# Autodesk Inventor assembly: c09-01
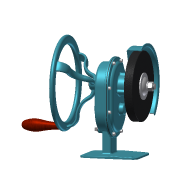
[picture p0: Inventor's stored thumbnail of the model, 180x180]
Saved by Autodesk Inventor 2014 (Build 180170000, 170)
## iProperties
Created: 2010-12
Part Number: c09-01
Document SubType Name: Assembly
Designer: Thom Tremblay
Author: Thom Tremblay
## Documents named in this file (27)
- C:\Inventor 2014 Essentials\Assemblies\Chapter 09\c09-01.iam
- C:\Inventor 2014 Essentials\Content Center Files\en-US\ANSI B93.98M\ANSI_B93.98M - 15x35x7-Type 2.ipt
- C:\Inventor 2014 Essentials\Content Center Files\en-US\SKF B - angular contact\SKF B7202 BE.ipt
- C:\Inventor 2014 Essentials\Content Center Files\en-US\IS 7483\IS 7483 - M4 x 8.ipt
- C:\Inventor 2014 Essentials\Content Center Files\en-US\ISO 2795  F\ISO 2795 - 10 x 14 x 10F.ipt
- C:\Inventor 2014 Essentials\Content Center Files\en-US\STN 022930\STN 022930 - 10.ipt
- C:\Inventor 2014 Essentials\Content Center Files\en-US\STN 022930\STN 022930 - 15.ipt
- C:\Inventor 2014 Essentials\Content Center Files\en-US\DIN 128\DIN 128 - A12.ipt
- C:\Inventor 2014 Essentials\Content Center Files\en-US\ISO 4032\ISO 4032 - M12ISO.ipt
- C:\Inventor 2014 Essentials\Content Center Files\en-US\ISO 4145 T8\ISO 4145 Plug T8 1_8.ipt
- C:\Inventor 2014 Essentials\Parts\Chapter 09\c09-01.ipt
- C:\Inventor 2014 Essentials\Parts\Chapter 09\c09-02.ipt
- C:\Inventor 2014 Essentials\Parts\Chapter 09\c09-03.ipt
- C:\Inventor 2014 Essentials\Parts\Chapter 09\c09-04.ipt
- C:\Inventor 2014 Essentials\Parts\Chapter 09\c09-05.ipt
- C:\Inventor 2014 Essentials\Parts\Chapter 09\c09-08.ipt
- C:\Inventor 2014 Essentials\Parts\Chapter 09\c09-06.ipt
- C:\Inventor 2014 Essentials\Parts\Chapter 09\c09-07.ipt
- C:\Inventor 2014 Essentials\Assemblies\Chapter 09\Design Accelerators\Shaft c09-01.iam
- C:\Inventor 2014 Essentials\Assemblies\Chapter 09\Design Accelerators\Shaft c09-02.iam
- C:\Inventor 2014 Essentials\Assemblies\Chapter 09\Design Accelerators\Shaft c09-03.iam
- C:\Inventor 2014 Essentials\Assemblies\Chapter 09\Design Accelerators\Cut Gear c09-01.iam
- C:\Inventor 2014 Essentials\Assemblies\Chapter 09\Design Accelerators\Cut Gear c09-02.iam
- C:\Inventor 2014 Essentials\Assemblies\Chapter 09\Design Accelerators\Spur Gear c09-01.iam
- C:\Inventor 2014 Essentials\Assemblies\Chapter 09\Design Accelerators\Key Connection c09-01.iam
- C:\Inventor 2014 Essentials\Assemblies\Chapter 09\Design Accelerators\Bolted Connection c09-01.iam
- C:\Inventor 2014 Essentials\Assemblies\Chapter 09\Design Accelerators\Bolted Connection c09-02.iam
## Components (31 placed, 24 different names)
1. c09-01:1 — Insert:1, Flush:3, Insert:27, Insert:28, Insert:39, Angle:19
2. c09-02:1 — Insert:1, Insert:17, Insert:18, Insert:25, Insert:26, Insert:40, Angle:19, Mate:18, Mate:19
3. ANSI/B93.98M 15x35x7-Type 2:1 — Insert:40
4. c09-03:1 — Flush:3
5. c09-04:1 — Insert:10, Angle:17, Insert:49, Mate:16, Angle:20
6. c09-05:1 — Insert:10
7. c09-08:1 — Insert:13, Insert:16, Insert:48
8. c09-08:2 — Insert:13
9. c09-06:1 — Insert:16, Angle:11
10. c09-07:1 — Insert:17, Insert:18
11. SKF B- Angular contact SKF B7202 BE:1 — Insert:25, Insert:45
12. IS 7483 M4 x 8:1
13. IS 7483 M4 x 8:2
14. ISO 2795 (Flanged) 10 x 14 x 10:1 — Insert:26
15. ISO 2795 (Flanged) 10 x 14 x 10:2 — Insert:27, Insert:46
16. ISO 2795 (Flanged) 10 x 14 x 10:3 — Insert:28, Insert:41
17. STN 022930 10:1 — Angle:16
18. STN 022930 15:1
19. STN 022930 15:2
20. DIN 128 A12:1 — Angle:10
21. ISO 4032 M12:1 — Angle:10, Angle:11, Angle:18
22. ISO 4145 Plug T8 1/8:1 — Insert:39
23. Input Shaft [sub-assembly] — Insert:41, Angle:16, Angle:17, Insert:49, Mate:17, Rotation:1, Rotation:2
24. Output Shaft:2 [sub-assembly] — Insert:45, Flush:4, Insert:48, Angle:18, Rotation:2
25. Transfer Shaft:1 [sub-assembly] — Insert:46, Mate:12, Flush:5, Angle:14, Mate:13, Angle:15, Rotation:1, Rotation:3
26. Cut Gear:1 [sub-assembly]
27. Cut Gear:2 [sub-assembly]
28. Cut Gear:3 [sub-assembly] — Mate:12, Flush:4, Angle:15, Rotation:3
29. Key Connection:1 [sub-assembly] — Flush:5, Angle:14, Mate:13
30. Housing Bolts:1 [sub-assembly] — Mate:18, Mate:19
31. Wheel Bolt [sub-assembly] — Mate:16, Mate:17, Angle:20
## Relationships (38: Insert 17, Angle 9, Mate 6, Flush 3, RelateRotation 3)
- Insert:1: c09-01:1 ↔ c09-02:1
- Flush:3: c09-01:1 ↔ c09-03:1
- Insert:10: c09-04:1 ↔ c09-05:1
- Insert:13: c09-08:1 ↔ c09-08:2
- Insert:16: c09-08:1 ↔ c09-06:1
- Insert:17: c09-02:1 ↔ c09-07:1
- Insert:18: c09-02:1 ↔ c09-07:1
- Insert:25: c09-02:1 ↔ SKF B- Angular contact SKF B7202 BE:1
- Insert:26: c09-02:1 ↔ ISO 2795 (Flanged) 10 x 14 x 10:1
- Insert:27: c09-01:1 ↔ ISO 2795 (Flanged) 10 x 14 x 10:2
- Insert:28: c09-01:1 ↔ ISO 2795 (Flanged) 10 x 14 x 10:3
- Angle:10: DIN 128 A12:1 ↔ ISO 4032 M12:1
- Angle:11: c09-06:1 ↔ ISO 4032 M12:1
- Insert:39: c09-01:1 ↔ ISO 4145 Plug T8 1/8:1
- Insert:40: c09-02:1 ↔ ANSI/B93.98M 15x35x7-Type 2:1
- Insert:41: ISO 2795 (Flanged) 10 x 14 x 10:3 ↔ Input Shaft
- Insert:45: SKF B- Angular contact SKF B7202 BE:1 ↔ Output Shaft:2
- Insert:46: ISO 2795 (Flanged) 10 x 14 x 10:2 ↔ Transfer Shaft:1
- Mate:12: Transfer Shaft:1 ↔ Cut Gear:3
- Flush:4: Output Shaft:2 ↔ Cut Gear:3
- Flush:5: Transfer Shaft:1 ↔ Key Connection:1
- Angle:14: Transfer Shaft:1 ↔ Key Connection:1
- Mate:13: Transfer Shaft:1 ↔ Key Connection:1
- Angle:15: Transfer Shaft:1 ↔ Cut Gear:3
- Angle:16: STN 022930 10:1 ↔ Input Shaft
- Angle:17: c09-04:1 ↔ Input Shaft
- Insert:48: c09-08:1 ↔ Output Shaft:2
- Angle:18: ISO 4032 M12:1 ↔ Output Shaft:2
- Insert:49: c09-04:1 ↔ Input Shaft
- Mate:16: c09-04:1 ↔ Wheel Bolt
- Mate:17: Input Shaft ↔ Wheel Bolt
- Angle:19: c09-01:1 ↔ c09-02:1
- Rotation:1 [RelateRotation]: Input Shaft ↔ Transfer Shaft:1
- Rotation:2 [RelateRotation]: Input Shaft ↔ Output Shaft:2
- Rotation:3 [RelateRotation]: Transfer Shaft:1 ↔ Cut Gear:3
- Mate:18: c09-02:1 ↔ Housing Bolts:1
- Mate:19: c09-02:1 ↔ Housing Bolts:1
- Angle:20: c09-04:1 ↔ Wheel Bolt
